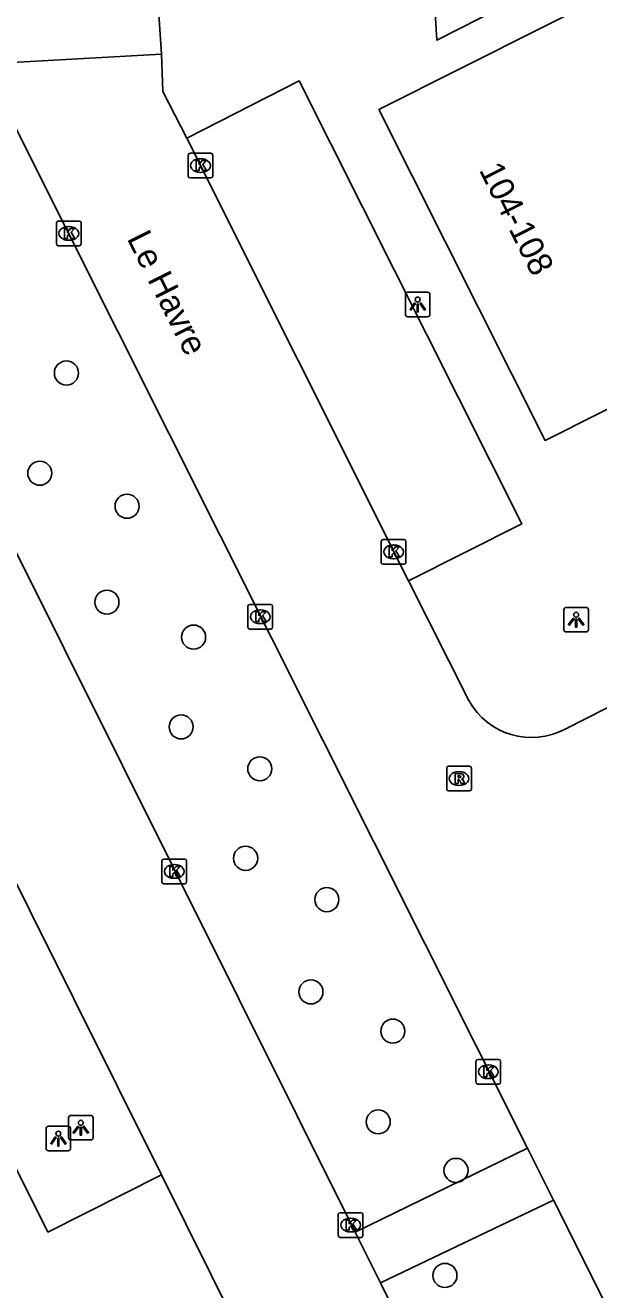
# Model space of a CAD drawing. Extents: x 158461 to 159795, y 387220 to 388672.
# Drawn here: x 159036.6 to 159059.9, y 387597.3 to 387648.6 of the extents above; entities that cross this region are included whole.
import ezdxf

# ---------------------------------------------------------------- set-up
doc = ezdxf.new("R2010")
doc.units = 0
for name, color, linetype in [('IMGEO_Boom', 7, 'Continuous'), ('IMGEO_Kolk', 7, 'Continuous'), ('IMGEO_Lichtpunt', 7, 'Continuous'), ('IMGEO_Openbare_ruimte_label', 7, 'Continuous'), ('IMGEO_Pand', 7, 'Continuous'), ('IMGEO_Pand_nummerreeks', 7, 'Continuous'), ('IMGEO_Rijbaan_lokaal_open', 7, 'Continuous'), ('IMGEO_Rioolput', 7, 'Continuous'), ('IMGEO_Voetpad_open', 7, 'Continuous')]:
    doc.layers.add(name, color=color, linetype=linetype)

msp = doc.modelspace()

# ---------------------------------------------------------------- linework, layer by layer
at = {"layer": 'IMGEO_Boom'}
for centre in [(159038.303, 387634.492), (159037.221, 387630.423), (159040.767, 387629.084), (159039.949, 387625.188), (159043.471, 387623.769), (159042.964, 387620.124), (159046.159, 387618.421), (159045.584, 387614.787), (159048.884, 387613.109), (159048.236, 387609.364), (159051.563, 387607.77), (159050.97, 387604.086), (159054.13, 387602.115), (159053.681, 387597.85)]:
    msp.add_circle(centre, 0.489, dxfattribs=at)
at = {"layer": 'IMGEO_Kolk'}
for p, q in [((159043.249, 387642.489), (159043.249, 387643.341)), ((159043.324, 387643.415), (159044.176, 387643.415)), ((159043.737, 387643.195), (159043.762, 387643.195)), ((159044.25, 387643.341), (159044.25, 387642.489)), ((159043.76, 387642.635), (159043.735, 387642.635)), ((159044.176, 387642.415), (159043.324, 387642.415)), ((159037.9, 387639.734), (159037.9, 387640.586)), ((159037.975, 387640.66), (159038.827, 387640.66)), ((159038.901, 387640.586), (159038.901, 387639.734)), ((159038.388, 387640.44), (159038.413, 387640.44)), ((159038.827, 387639.66), (159037.975, 387639.66)), ((159038.411, 387639.88), (159038.386, 387639.88)), ((159051.17, 387627.729), (159052.022, 387627.729)), ((159051.095, 387626.803), (159051.095, 387627.655)), ((159051.583, 387627.509), (159051.608, 387627.509)), ((159052.096, 387627.655), (159052.096, 387626.803)), ((159052.022, 387626.729), (159051.17, 387626.729)), ((159051.606, 387626.949), (159051.581, 387626.949)), ((159045.678, 387624.17), (159045.678, 387625.022)), ((159045.753, 387625.096), (159046.605, 387625.096)), ((159046.166, 387624.876), (159046.191, 387624.876)), ((159046.679, 387625.022), (159046.679, 387624.17)), ((159046.605, 387624.096), (159045.753, 387624.096)), ((159046.189, 387624.316), (159046.164, 387624.316)), ((159042.184, 387613.829), (159042.184, 387614.681)), ((159042.259, 387614.755), (159043.111, 387614.755)), ((159042.672, 387614.535), (159042.697, 387614.535)), ((159043.185, 387614.681), (159043.185, 387613.829)), ((159042.695, 387613.975), (159042.67, 387613.975)), ((159043.111, 387613.755), (159042.259, 387613.755)), ((159054.942, 387605.694), (159054.942, 387606.546)), ((159055.017, 387606.62), (159055.869, 387606.62)), ((159055.43, 387606.4), (159055.455, 387606.4)), ((159055.943, 387606.546), (159055.943, 387605.694)), ((159055.869, 387605.62), (159055.017, 387605.62)), ((159055.453, 387605.84), (159055.428, 387605.84)), ((159049.348, 387599.47), (159049.348, 387600.322)), ((159049.423, 387600.396), (159050.275, 387600.396)), ((159049.836, 387600.176), (159049.861, 387600.176)), ((159050.349, 387600.322), (159050.349, 387599.47)), ((159049.859, 387599.616), (159049.834, 387599.616)), ((159050.275, 387599.396), (159049.423, 387599.396))]:
    msp.add_line(p, q, dxfattribs=at)
for points in [[(159043.249, 387642.489), (159043.249, 387643.341)], [(159043.324, 387643.415), (159044.176, 387643.415)], [(159043.57, 387643.115), (159043.693, 387643.115), (159043.693, 387642.964), (159043.823, 387643.115), (159043.987, 387643.115), (159043.841, 387642.964), (159043.994, 387642.715), (159043.842, 387642.715), (159043.757, 387642.879), (159043.693, 387642.812), (159043.693, 387642.715), (159043.57, 387642.715), (159043.57, 387643.115)], [(159044.25, 387643.341), (159044.25, 387642.489)], [(159044.176, 387642.415), (159043.324, 387642.415)], [(159037.9, 387639.734), (159037.9, 387640.586)], [(159037.975, 387640.66), (159038.827, 387640.66)], [(159038.901, 387640.586), (159038.901, 387639.734)], [(159038.221, 387640.36), (159038.344, 387640.36), (159038.344, 387640.209), (159038.474, 387640.36), (159038.638, 387640.36), (159038.492, 387640.209), (159038.645, 387639.96), (159038.493, 387639.96), (159038.408, 387640.124), (159038.344, 387640.057), (159038.344, 387639.96), (159038.221, 387639.96), (159038.221, 387640.36)], [(159038.827, 387639.66), (159037.975, 387639.66)], [(159051.17, 387627.729), (159052.022, 387627.729)], [(159051.095, 387626.803), (159051.095, 387627.655)], [(159051.416, 387627.429), (159051.539, 387627.429), (159051.539, 387627.278), (159051.669, 387627.429), (159051.833, 387627.429), (159051.687, 387627.278), (159051.84, 387627.029), (159051.688, 387627.029), (159051.603, 387627.193), (159051.539, 387627.126), (159051.539, 387627.029), (159051.416, 387627.029), (159051.416, 387627.429)], [(159052.096, 387627.655), (159052.096, 387626.803)], [(159052.022, 387626.729), (159051.17, 387626.729)], [(159045.678, 387624.17), (159045.678, 387625.022)], [(159045.753, 387625.096), (159046.605, 387625.096)], [(159045.999, 387624.796), (159046.122, 387624.796), (159046.122, 387624.645), (159046.252, 387624.796), (159046.416, 387624.796), (159046.27, 387624.645), (159046.423, 387624.396), (159046.271, 387624.396), (159046.186, 387624.56), (159046.122, 387624.493), (159046.122, 387624.396), (159045.999, 387624.396), (159045.999, 387624.796)], [(159046.679, 387625.022), (159046.679, 387624.17)], [(159046.605, 387624.096), (159045.753, 387624.096)], [(159042.184, 387613.829), (159042.184, 387614.681)], [(159042.259, 387614.755), (159043.111, 387614.755)], [(159042.505, 387614.455), (159042.628, 387614.455), (159042.628, 387614.304), (159042.758, 387614.455), (159042.922, 387614.455), (159042.776, 387614.304), (159042.929, 387614.055), (159042.777, 387614.055), (159042.692, 387614.219), (159042.628, 387614.152), (159042.628, 387614.055), (159042.505, 387614.055), (159042.505, 387614.455)], [(159043.185, 387614.681), (159043.185, 387613.829)], [(159043.111, 387613.755), (159042.259, 387613.755)], [(159054.942, 387605.694), (159054.942, 387606.546)], [(159055.017, 387606.62), (159055.869, 387606.62)], [(159055.263, 387606.32), (159055.386, 387606.32), (159055.386, 387606.169), (159055.516, 387606.32), (159055.68, 387606.32), (159055.534, 387606.169), (159055.687, 387605.92), (159055.535, 387605.92), (159055.45, 387606.084), (159055.386, 387606.017), (159055.386, 387605.92), (159055.263, 387605.92), (159055.263, 387606.32)], [(159055.943, 387606.546), (159055.943, 387605.694)], [(159055.869, 387605.62), (159055.017, 387605.62)], [(159049.348, 387599.47), (159049.348, 387600.322)], [(159049.423, 387600.396), (159050.275, 387600.396)], [(159049.669, 387600.096), (159049.792, 387600.096), (159049.792, 387599.945), (159049.922, 387600.096), (159050.086, 387600.096), (159049.94, 387599.945), (159050.093, 387599.696), (159049.941, 387599.696), (159049.856, 387599.86), (159049.792, 387599.793), (159049.792, 387599.696), (159049.669, 387599.696), (159049.669, 387600.096)], [(159050.349, 387600.322), (159050.349, 387599.47)], [(159050.275, 387599.396), (159049.423, 387599.396)]]:
    msp.add_lwpolyline(points, dxfattribs=at)
for centre, start, end in [((159043.326, 387643.339), 91.552, 178.448), ((159043.326, 387643.339), 91.552, 178.448), ((159044.174, 387643.339), 1.552, 88.448), ((159044.174, 387643.339), 1.552, 88.448), ((159043.326, 387642.491), 181.552, 268.448), ((159043.326, 387642.491), 181.552, 268.448), ((159044.174, 387642.491), 271.552, 358.448), ((159044.174, 387642.491), 271.552, 358.448), ((159037.977, 387640.584), 91.552, 178.448), ((159037.977, 387640.584), 91.552, 178.448), ((159038.825, 387640.584), 1.552, 88.448), ((159038.825, 387640.584), 1.552, 88.448), ((159037.977, 387639.736), 181.552, 268.448), ((159037.977, 387639.736), 181.552, 268.448), ((159038.825, 387639.736), 271.552, 358.448), ((159038.825, 387639.736), 271.552, 358.448), ((159051.172, 387627.653), 91.552, 178.448), ((159051.172, 387627.653), 91.552, 178.448), ((159052.02, 387627.653), 1.552, 88.448), ((159052.02, 387627.653), 1.552, 88.448), ((159051.172, 387626.805), 181.552, 268.448), ((159051.172, 387626.805), 181.552, 268.448), ((159052.02, 387626.805), 271.552, 358.448), ((159052.02, 387626.805), 271.552, 358.448), ((159045.755, 387625.02), 91.552, 178.448), ((159045.755, 387625.02), 91.552, 178.448), ((159046.603, 387625.02), 1.552, 88.448), ((159046.603, 387625.02), 1.552, 88.448), ((159045.755, 387624.172), 181.552, 268.448), ((159045.755, 387624.172), 181.552, 268.448), ((159046.603, 387624.172), 271.552, 358.448), ((159046.603, 387624.172), 271.552, 358.448), ((159042.261, 387614.679), 91.552, 178.448), ((159042.261, 387614.679), 91.552, 178.448), ((159043.109, 387614.679), 1.552, 88.448), ((159043.109, 387614.679), 1.552, 88.448), ((159042.261, 387613.831), 181.552, 268.448), ((159042.261, 387613.831), 181.552, 268.448), ((159043.109, 387613.831), 271.552, 358.448), ((159043.109, 387613.831), 271.552, 358.448), ((159055.019, 387606.544), 91.552, 178.448), ((159055.019, 387606.544), 91.552, 178.448), ((159055.867, 387606.544), 1.552, 88.448), ((159055.867, 387606.544), 1.552, 88.448), ((159055.019, 387605.696), 181.552, 268.448), ((159055.019, 387605.696), 181.552, 268.448), ((159055.867, 387605.696), 271.552, 358.448), ((159055.867, 387605.696), 271.552, 358.448), ((159049.425, 387600.32), 91.552, 178.448), ((159049.425, 387600.32), 91.552, 178.448), ((159050.273, 387600.32), 1.552, 88.448), ((159050.273, 387600.32), 1.552, 88.448), ((159049.425, 387599.472), 181.552, 268.448), ((159049.425, 387599.472), 181.552, 268.448), ((159050.273, 387599.472), 271.552, 358.448), ((159050.273, 387599.472), 271.552, 358.448)]:
    msp.add_arc(centre, 0.0765, start, end, dxfattribs=at)
for centre, major_axis, ratio, start_param, end_param in [((159043.736, 387642.915), (-0.387, 0.002), 0.722429, 4.712389, 7.853982), ((159043.761, 387642.915), (-0.39, 0.002), 0.717154, 1.570796, 4.712389), ((159038.387, 387640.16), (-0.387, 0.002), 0.722429, 4.712389, 7.853982), ((159038.412, 387640.16), (-0.39, 0.002), 0.717154, 1.570796, 4.712389), ((159051.582, 387627.229), (-0.387, 0.002), 0.722429, 4.712389, 7.853982), ((159051.607, 387627.229), (-0.39, 0.002), 0.717154, 1.570796, 4.712389), ((159046.165, 387624.596), (-0.387, 0.002), 0.722429, 4.712389, 7.853982), ((159046.19, 387624.596), (-0.39, 0.002), 0.717154, 1.570796, 4.712389), ((159042.671, 387614.255), (-0.387, 0.002), 0.722429, 4.712389, 7.853982), ((159042.696, 387614.255), (-0.39, 0.002), 0.717154, 1.570796, 4.712389), ((159055.429, 387606.12), (-0.387, 0.002), 0.722429, 4.712389, 7.853982), ((159055.454, 387606.12), (-0.39, 0.002), 0.717154, 1.570796, 4.712389), ((159049.835, 387599.896), (-0.387, 0.002), 0.722429, 4.712389, 7.853982), ((159049.86, 387599.896), (-0.39, 0.002), 0.717154, 1.570796, 4.712389)]:
    msp.add_ellipse(centre, major_axis=major_axis, ratio=ratio, start_param=start_param, end_param=end_param, dxfattribs=at)
at = {"layer": 'IMGEO_Lichtpunt'}
for p, q in [((159052.075, 387637.676), (159052.075, 387636.869)), ((159052.075, 387637.676), (159052.075, 387636.869)), ((159052.977, 387637.771), (159052.169, 387637.771)), ((159052.977, 387637.771), (159052.169, 387637.771)), ((159053.071, 387636.869), (159053.071, 387637.676)), ((159053.071, 387636.869), (159053.071, 387637.676)), ((159052.169, 387636.775), (159052.977, 387636.775)), ((159052.169, 387636.775), (159052.977, 387636.775)), ((159058.513, 387624.878), (159058.513, 387624.071)), ((159058.513, 387624.878), (159058.513, 387624.071)), ((159059.415, 387624.973), (159058.607, 387624.973)), ((159059.415, 387624.973), (159058.607, 387624.973)), ((159059.509, 387624.071), (159059.509, 387624.878)), ((159059.509, 387624.071), (159059.509, 387624.878)), ((159058.607, 387623.977), (159059.415, 387623.977)), ((159058.607, 387623.977), (159059.415, 387623.977)), ((159038.39, 387604.251), (159038.39, 387603.444)), ((159038.39, 387604.251), (159038.39, 387603.444)), ((159039.292, 387604.346), (159038.484, 387604.346)), ((159039.292, 387604.346), (159038.484, 387604.346)), ((159039.386, 387603.444), (159039.386, 387604.251)), ((159039.386, 387603.444), (159039.386, 387604.251)), ((159037.479, 387603.811), (159037.479, 387603.004)), ((159037.479, 387603.811), (159037.479, 387603.004)), ((159038.381, 387603.906), (159037.573, 387603.906)), ((159038.381, 387603.906), (159037.573, 387603.906)), ((159038.475, 387603.004), (159038.475, 387603.811)), ((159038.475, 387603.004), (159038.475, 387603.811)), ((159038.484, 387603.35), (159039.292, 387603.35)), ((159038.484, 387603.35), (159039.292, 387603.35)), ((159037.573, 387602.91), (159038.381, 387602.91)), ((159037.573, 387602.91), (159038.381, 387602.91))]:
    msp.add_line(p, q, dxfattribs=at)
for points in [[(159052.449, 387637.34), (159052.488, 387637.312), (159052.3, 387637.05), (159052.262, 387637.077), (159052.449, 387637.34)], [(159052.551, 387637.292), (159052.598, 387637.292), (159052.598, 387636.97), (159052.551, 387636.97), (159052.551, 387637.292)], [(159052.661, 387637.312), (159052.699, 387637.339), (159052.886, 387637.077), (159052.847, 387637.049), (159052.661, 387637.312)], [(159058.887, 387624.542), (159058.926, 387624.514), (159058.738, 387624.252), (159058.7, 387624.279), (159058.887, 387624.542)], [(159058.989, 387624.494), (159059.036, 387624.494), (159059.036, 387624.172), (159058.989, 387624.172), (159058.989, 387624.494)], [(159059.099, 387624.514), (159059.137, 387624.541), (159059.324, 387624.279), (159059.285, 387624.251), (159059.099, 387624.514)], [(159038.764, 387603.915), (159038.803, 387603.887), (159038.615, 387603.625), (159038.577, 387603.652), (159038.764, 387603.915)], [(159038.866, 387603.867), (159038.913, 387603.867), (159038.913, 387603.545), (159038.866, 387603.545), (159038.866, 387603.867)], [(159038.976, 387603.887), (159039.014, 387603.914), (159039.201, 387603.652), (159039.162, 387603.624), (159038.976, 387603.887)], [(159037.853, 387603.475), (159037.892, 387603.447), (159037.704, 387603.185), (159037.666, 387603.212), (159037.853, 387603.475)], [(159037.955, 387603.427), (159038.002, 387603.427), (159038.002, 387603.105), (159037.955, 387603.105), (159037.955, 387603.427)], [(159038.065, 387603.447), (159038.103, 387603.474), (159038.29, 387603.212), (159038.251, 387603.184), (159038.065, 387603.447)]]:
    msp.add_lwpolyline(points, dxfattribs=at)
for centre in [(159052.574, 387637.474), (159059.012, 387624.676), (159038.889, 387604.049), (159037.978, 387603.609)]:
    msp.add_circle(centre, 0.0994, dxfattribs=at)
for centre, start, end in [((159052.169, 387637.676), 90, 180), ((159052.169, 387637.676), 90, 180), ((159052.977, 387637.676), 0, 90), ((159052.977, 387637.676), 0, 90), ((159052.169, 387636.869), 180, 270), ((159052.169, 387636.869), 180, 270), ((159052.977, 387636.869), 270, 0), ((159052.977, 387636.869), 270, 360), ((159058.607, 387624.878), 90, 180), ((159058.607, 387624.878), 90, 180), ((159059.415, 387624.878), 0, 90), ((159059.415, 387624.878), 0, 90), ((159058.607, 387624.071), 180, 270), ((159058.607, 387624.071), 180, 270), ((159059.415, 387624.071), 270, 0), ((159059.415, 387624.071), 270, 360), ((159038.484, 387604.251), 90, 180), ((159038.484, 387604.251), 90, 180), ((159039.292, 387604.251), 0, 90), ((159039.292, 387604.251), 0, 90), ((159037.573, 387603.811), 90, 180), ((159037.573, 387603.811), 90, 180), ((159038.381, 387603.811), 0, 90), ((159038.381, 387603.811), 0, 90), ((159038.484, 387603.444), 180, 270), ((159038.484, 387603.444), 180, 270), ((159039.292, 387603.444), 270, 0), ((159039.292, 387603.444), 270, 360), ((159037.573, 387603.004), 180, 270), ((159037.573, 387603.004), 180, 270), ((159038.381, 387603.004), 270, 0), ((159038.381, 387603.004), 270, 360)]:
    msp.add_arc(centre, 0.0946, start, end, dxfattribs=at)
at = {"layer": 'IMGEO_Pand'}
msp.add_lwpolyline([(159064.373, 387651.914), (159071.125, 387638.479), (159057.75, 387631.756), (159050.997, 387645.191), (159064.373, 387651.914)], dxfattribs=at)
at = {"layer": 'IMGEO_Rijbaan_lokaal_open'}
for points in [[(159041.984, 387650.094), (159042.168, 387647.445)], [(159018.981, 387648.425), (159042.17, 387601.935)], [(159042.168, 387647.445), (159036.101, 387647.097)], [(159042.168, 387647.445), (159042.221, 387645.918), (159043.202, 387644.022)], [(159026.374, 387647.012), (159050.035, 387599.601)], [(159057.036, 387603.022), (159036.238, 387644.461), (159036.145, 387646.208)], [(159052.206, 387626.058), (159043.202, 387644.022)], [(159058.563, 387620.036), (159080.094, 387630.961)], [(159052.206, 387626.058), (159054.656, 387621.191)], [(159050.035, 387599.601), (159057.036, 387603.022)], [(159057.036, 387603.022), (159058.095, 387600.913)], [(159042.17, 387601.935), (159048.183, 387589.84)], [(159058.095, 387600.913), (159051.06, 387597.547)], [(159072.299, 387572.612), (159058.095, 387600.913)], [(159051.06, 387597.547), (159050.035, 387599.601)], [(159051.06, 387597.547), (159065.368, 387568.879)]]:
    msp.add_lwpolyline(points, dxfattribs=at)
msp.add_arc((159057.194, 387622.59), 2.898, 208.8617, 298.2005, dxfattribs=at)
at = {"layer": 'IMGEO_Rioolput'}
for p, q in [((159053.753, 387617.599), (159053.753, 387618.451)), ((159053.828, 387618.525), (159054.68, 387618.525)), ((159054.754, 387618.451), (159054.754, 387617.599)), ((159054.241, 387618.305), (159054.266, 387618.305)), ((159054.68, 387617.525), (159053.828, 387617.525)), ((159054.264, 387617.745), (159054.239, 387617.745))]:
    msp.add_line(p, q, dxfattribs=at)
for points in [[(159053.753, 387617.599), (159053.753, 387618.451)], [(159053.828, 387618.525), (159054.68, 387618.525)], [(159054.754, 387618.451), (159054.754, 387617.599)], [(159054.342, 387618.223), (159054.09, 387618.225), (159054.09, 387617.825)], [(159054.09, 387617.825), (159054.214, 387617.825), (159054.214, 387617.987), (159054.225, 387617.987)], [(159054.268, 387618.144), (159054.214, 387618.144), (159054.214, 387618.063)], [(159054.214, 387618.063), (159054.266, 387618.063)], [(159054.272, 387617.958), (159054.343, 387617.825), (159054.483, 387617.825), (159054.418, 387617.951)], [(159054.68, 387617.525), (159053.828, 387617.525)]]:
    msp.add_lwpolyline(points, dxfattribs=at)
for centre, radius, start, end in [((159053.83, 387618.449), 0.0765, 91.552, 178.448), ((159053.83, 387618.449), 0.0765, 91.552, 178.448), ((159054.678, 387618.449), 0.0765, 1.552, 88.448), ((159054.678, 387618.449), 0.0765, 1.552, 88.448), ((159054.224, 387617.934), 0.0533, 26.0293, 88.6989), ((159054.25, 387618.252), 0.19, 274.7715, 282.9687), ((159054.274, 387618.048), 0.0964, 77.0061, 93.1865), ((159054.288, 387618.105), 0.0378, 276.6634, 79.6772), ((159054.341, 387618.113), 0.109, 350.3612, 89.416), ((159054.339, 387618.113), 0.112, 277.5842, 350.9817), ((159054.323, 387617.898), 0.108, 29.5134, 73.7905), ((159053.83, 387617.601), 0.0765, 181.552, 268.448), ((159053.83, 387617.601), 0.0765, 181.552, 268.448), ((159054.678, 387617.601), 0.0765, 271.552, 358.448), ((159054.678, 387617.601), 0.0765, 271.552, 358.448)]:
    msp.add_arc(centre, radius, start, end, dxfattribs=at)
for centre, major_axis, ratio, start_param, end_param in [((159054.24, 387618.025), (-0.387, 0.002), 0.722429, 4.712389, 7.853982), ((159054.265, 387618.025), (-0.39, 0.002), 0.717154, 1.570796, 4.712389)]:
    msp.add_ellipse(centre, major_axis=major_axis, ratio=ratio, start_param=start_param, end_param=end_param, dxfattribs=at)
at = {"layer": 'IMGEO_Voetpad_open'}
for points in [[(159063.669, 387657.684), (159063.915, 387653.384), (159053.358, 387648.007), (159052.797, 387657.162), (159063.669, 387657.684)], [(159042.17, 387601.935), (159037.554, 387599.613), (159014.372, 387646.136), (159018.981, 387648.425)], [(159043.202, 387644.022), (159047.765, 387646.352), (159056.798, 387628.366), (159052.206, 387626.058)]]:
    msp.add_lwpolyline(points, dxfattribs=at)

# ---------------------------------------------------------------- texts
at = {"layer": 'IMGEO_Openbare_ruimte_label'}
msp.add_text('Le Havre', height=1, rotation=296.6675, dxfattribs=at).set_placement((159040.746, 387639.957))
at = {"layer": 'IMGEO_Pand_nummerreeks'}
msp.add_text('104-108', height=1, rotation=296.686, dxfattribs=at).set_placement((159055.05, 387642.738))

doc.saveas('drawing.dxf')
